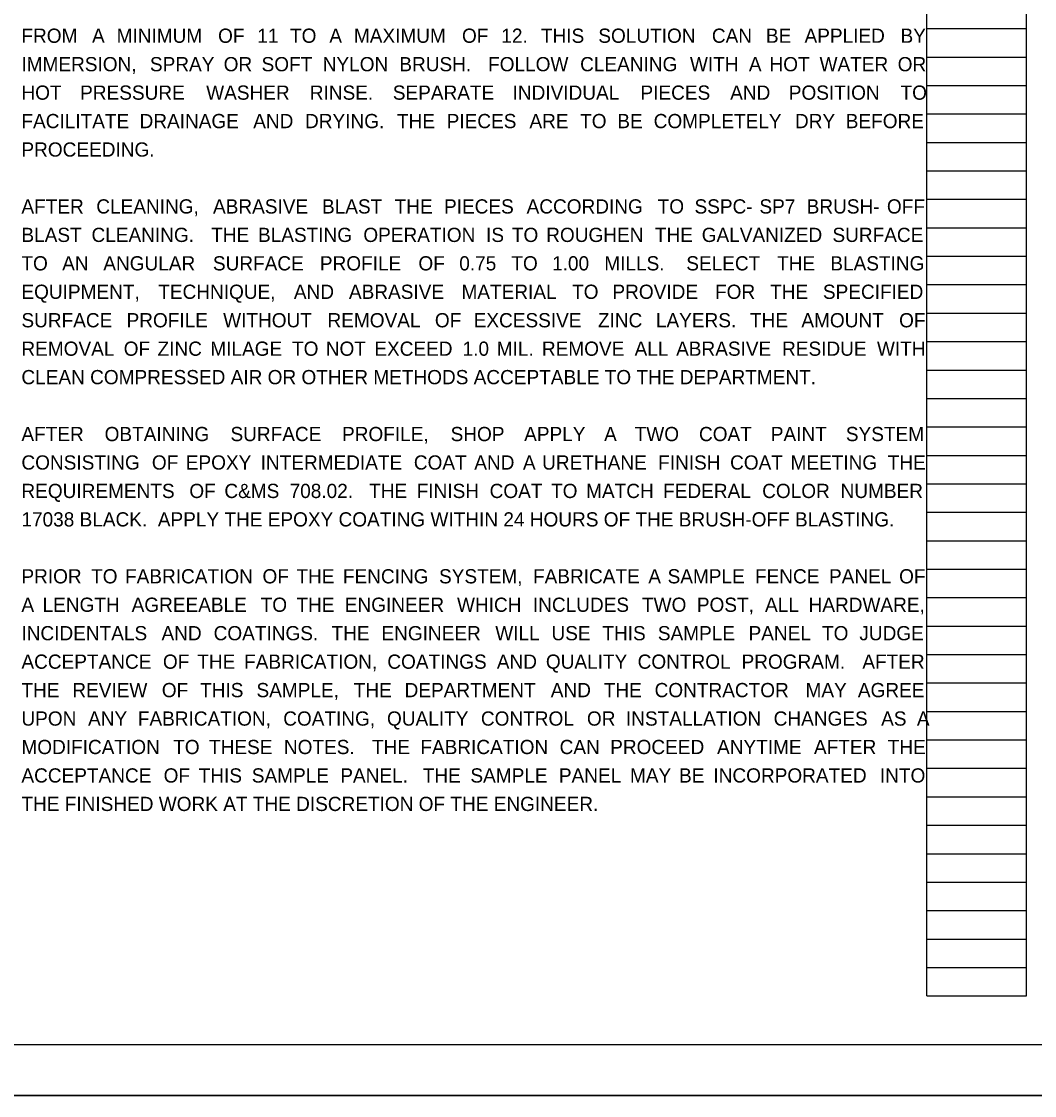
# Model space of a CAD drawing. Extents: x 0 to 34, y 0 to 22.
# Drawn here: x 12.29 to 22.27, y 0 to 10.57 of the extents above; entities that cross this region are included whole.
import ezdxf

# ---------------------------------------------------------------- set-up
doc = ezdxf.new("R2010")
doc.units = 0
for name, color, linetype in [('SC_Scratch1', 7, 'Continuous'), ('SH_Border', 7, 'Continuous'), ('SH_Cut_Line', 7, 'Continuous'), ('SH_Text', 7, 'Continuous')]:
    doc.layers.add(name, color=color, linetype=linetype)

msp = doc.modelspace()

# ---------------------------------------------------------------- linework, layer by layer
at = {"layer": 'SC_Scratch1'}
for p, q in [((21.207, 0.98), (21.207, 21.14)), ((22.187, 0.98), (22.187, 21.14)), ((21.207, 10.5), (22.187, 10.5)), ((21.207, 10.22), (22.187, 10.22)), ((21.207, 9.94), (22.187, 9.94)), ((21.207, 9.66), (22.187, 9.66)), ((21.207, 9.38), (22.187, 9.38)), ((21.207, 9.1), (22.187, 9.1)), ((21.207, 8.82), (22.187, 8.82)), ((21.207, 8.54), (22.187, 8.54)), ((21.207, 8.26), (22.187, 8.26)), ((21.207, 7.98), (22.187, 7.98)), ((21.207, 7.7), (22.187, 7.7)), ((21.207, 7.42), (22.187, 7.42)), ((21.207, 7.14), (22.187, 7.14)), ((21.207, 6.86), (22.187, 6.86)), ((21.207, 6.58), (22.187, 6.58)), ((21.207, 6.3), (22.187, 6.3)), ((21.207, 6.02), (22.187, 6.02)), ((21.207, 5.74), (22.187, 5.74)), ((21.207, 5.46), (22.187, 5.46)), ((21.207, 5.18), (22.187, 5.18)), ((21.207, 4.9), (22.187, 4.9)), ((21.207, 4.62), (22.187, 4.62)), ((21.207, 4.34), (22.187, 4.34)), ((21.207, 4.06), (22.187, 4.06)), ((21.207, 3.78), (22.187, 3.78)), ((21.207, 3.5), (22.187, 3.5)), ((21.207, 3.22), (22.187, 3.22)), ((21.207, 2.94), (22.187, 2.94)), ((21.207, 2.66), (22.187, 2.66)), ((21.207, 2.38), (22.187, 2.38)), ((21.207, 2.1), (22.187, 2.1)), ((21.207, 1.82), (22.187, 1.82)), ((21.207, 1.54), (22.187, 1.54)), ((21.207, 1.26), (22.187, 1.26)), ((21.207, 0.98), (22.187, 0.98))]:
    msp.add_line(p, q, dxfattribs=at)
msp.add_lwpolyline([(0, 22), (34, 22), (34, 0), (0, 0)], close=True, dxfattribs=at)
at = {"layer": 'SH_Border'}
msp.add_lwpolyline([(1.5, 21.5), (33.5, 21.5), (33.5, 0.5), (1.5, 0.5)], close=True, dxfattribs=at)
at = {"layer": 'SH_Cut_Line'}
msp.add_lwpolyline([(0, 0), (34, 0), (34, 22), (0, 22)], close=True, dxfattribs=at)

# ---------------------------------------------------------------- texts
at = {"layer": 'SH_Text'}
for s, p in [('FROM ', (12.293, 10.36)), ('A ', (12.988, 10.36)), ('MINIMUM ', (13.23, 10.36)), ('OF ', (14.229, 10.36)), ('11 ', (14.615, 10.36)), ('TO ', (14.937, 10.36)), ('A ', (15.324, 10.36)), ('MAXIMUM ', (15.566, 10.36)), ('OF ', (16.63, 10.36)), ('12. ', (17.017, 10.36)), ('THIS ', (17.407, 10.36)), ('SOLUTION ', (17.972, 10.36)), ('CAN ', (19.09, 10.36)), ('BE ', (19.622, 10.36)), ('APPLIED ', (20.002, 10.36)), ('BY ', (20.947, 10.36)), ('IMMERSION, ', (12.293, 10.08)), ('SPRAY ', (13.558, 10.08)), ('OR ', (14.284, 10.08)), ('SOFT ', (14.657, 10.08)), ('NYLON ', (15.259, 10.08)), ('BRUSH.  ', (16.013, 10.08)), ('FOLLOW ', (16.887, 10.08)), ('CLEANING ', (17.793, 10.08)), ('WITH ', (18.874, 10.08)), ('A ', (19.454, 10.08)), ('HOT ', (19.657, 10.08)), ('WATER ', (20.15, 10.08)), ('OR ', (20.919, 10.08)), ('HOT ', (12.293, 9.8)), ('PRESSURE ', (12.871, 9.8)), ('WASHER ', (14.112, 9.8)), ('RINSE. ', (15.132, 9.8)), ('SEPARATE ', (15.949, 9.8)), ('INDIVIDUAL ', (17.128, 9.8)), ('PIECES ', (18.387, 9.8)), ('AND ', (19.27, 9.8)), ('POSITION ', (19.847, 9.8)), ('TO ', (20.947, 9.8)), ('FACILITATE ', (12.293, 9.52)), ('DRAINAGE ', (13.456, 9.52)), ('AND ', (14.575, 9.52)), ('DRYING. ', (15.085, 9.52)), ('THE ', (15.99, 9.52)), ('PIECES ', (16.479, 9.52)), ('ARE ', (17.294, 9.52)), ('TO ', (17.793, 9.52)), ('BE ', (18.159, 9.52)), ('COMPLETELY ', (18.517, 9.52)), ('DRY ', (19.908, 9.52)), ('BEFORE ', (20.408, 9.52)), ('PROCEEDING. ', (12.293, 9.24)), ('AFTER ', (12.293, 8.68)), ('CLEANING, ', (13.03, 8.68)), ('ABRASIVE ', (14.179, 8.68)), ('BLAST ', (15.252, 8.68)), ('THE ', (15.967, 8.68)), ('PIECES ', (16.453, 8.68)), ('ACCORDING ', (17.266, 8.68)), ('TO ', (18.556, 8.68)), ('SSPC-', (18.919, 8.68)), ('SP7 ', (19.558, 8.68)), ('BRUSH-', (20.023, 8.68)), ('OFF ', (20.813, 8.68)), ('BLAST ', (12.293, 8.4)), ('CLEANING.  ', (12.983, 8.4)), ('THE ', (14.161, 8.4)), ('BLASTING ', (14.622, 8.4)), ('OPERATION ', (15.659, 8.4)), ('IS ', (16.867, 8.4)), ('TO ', (17.121, 8.4)), ('ROUGHEN ', (17.459, 8.4)), ('THE ', (18.529, 8.4)), ('GALVANIZED ', (18.99, 8.4)), ('SURFACE ', (20.277, 8.4)), ('TO ', (12.293, 8.12)), ('AN ', (12.694, 8.12)), ('ANGULAR ', (13.099, 8.12)), ('SURFACE ', (14.178, 8.12)), ('PROFILE ', (15.231, 8.12)), ('OF ', (16.201, 8.12)), ('0.75 ', (16.603, 8.12)), ('TO ', (17.116, 8.12)), ('1.00 ', (17.517, 8.12)), ('MILLS.  ', (18.031, 8.12)), ('SELECT ', (18.838, 8.12)), ('THE ', (19.732, 8.12)), ('BLASTING ', (20.256, 8.12)), ('EQUIPMENT, ', (12.293, 7.84)), ('TECHNIQUE, ', (13.64, 7.84)), ('AND ', (14.975, 7.84)), ('ABRASIVE ', (15.517, 7.84)), ('MATERIAL ', (16.625, 7.84)), ('TO ', (17.714, 7.84)), ('PROVIDE ', (18.111, 7.84)), ('FOR ', (19.121, 7.84)), ('THE ', (19.663, 7.84)), ('SPECIFIED ', (20.183, 7.84)), ('SURFACE ', (12.293, 7.56)), ('PROFILE ', (13.328, 7.56)), ('WITHOUT ', (14.279, 7.56)), ('REMOVAL ', (15.306, 7.56)), ('OF ', (16.363, 7.56)), ('EXCESSIVE ', (16.745, 7.56)), ('ZINC ', (17.968, 7.56)), ('LAYERS. ', (18.539, 7.56)), ('THE ', (19.465, 7.56)), ('AMOUNT ', (19.971, 7.56)), ('OF ', (20.933, 7.56)), ('REMOVAL ', (12.293, 7.28)), ('OF ', (13.3, 7.28)), ('ZINC ', (13.633, 7.28)), ('MILAGE ', (14.153, 7.28)), ('TO ', (14.957, 7.28)), ('NOT ', (15.289, 7.28)), ('EXCEED ', (15.767, 7.28)), ('1.0 ', (16.636, 7.28)), ('MIL. ', (16.972, 7.28)), ('REMOVE ', (17.417, 7.28)), ('ALL ', (18.329, 7.28)), ('ABRASIVE ', (18.738, 7.28)), ('RESIDUE ', (19.781, 7.28)), ('WITH ', (20.715, 7.28)), ('CLEAN COMPRESSED AIR OR OTHER METHODS ACCEPTABLE TO THE DEPARTMENT.', (12.293, 7)), ('AFTER ', (12.293, 6.44)), ('OBTAINING ', (13.112, 6.44)), ('SURFACE ', (14.351, 6.44)), ('PROFILE, ', (15.449, 6.44)), ('SHOP ', (16.518, 6.44)), ('APPLY ', (17.242, 6.44)), ('A ', (18.029, 6.44)), ('TWO ', (18.33, 6.44)), ('COAT ', (18.963, 6.44)), ('PAINT ', (19.67, 6.44)), ('SYSTEM ', (20.409, 6.44)), ('CONSISTING ', (12.293, 6.16)), ('OF ', (13.577, 6.16)), ('EPOXY ', (13.911, 6.16)), ('INTERMEDIATE ', (14.648, 6.16)), ('COAT ', (16.156, 6.16)), ('AND ', (16.751, 6.16)), ('A ', (17.23, 6.16)), ('URETHANE ', (17.419, 6.16)), ('FINISH ', (18.561, 6.16)), ('COAT ', (19.269, 6.16)), ('MEETING ', (19.864, 6.16)), ('THE ', (20.821, 6.16)), ('REQUIREMENTS ', (12.293, 5.88)), ('OF ', (13.946, 5.88)), ('C&MS ', (14.291, 5.88)), ('708.02.  ', (14.933, 5.88)), ('THE ', (15.716, 5.88)), ('FINISH ', (16.184, 5.88)), ('COAT ', (16.902, 5.88)), ('TO ', (17.507, 5.88)), ('MATCH ', (17.852, 5.88)), ('FEDERAL ', (18.61, 5.88)), ('COLOR ', (19.585, 5.88)), ('NUMBER ', (20.357, 5.88)), ('17038 BLACK.  APPLY THE EPOXY COATING WITHIN 24 HOURS OF THE BRUSH-OFF BLASTING. ', (12.293, 5.6)), ('PRIOR ', (12.293, 5.04)), ('TO ', (12.979, 5.04)), ('FABRICATION ', (13.313, 5.04)), ('OF ', (14.666, 5.04)), ('THE ', (15, 5.04)), ('FENCING ', (15.458, 5.04)), ('SYSTEM, ', (16.404, 5.04)), ('FABRICATE ', (17.329, 5.04)), ('A ', (18.464, 5.04)), ('SAMPLE ', (18.654, 5.04)), ('FENCE ', (19.514, 5.04)), ('PANEL ', (20.243, 5.04)), ('OF ', (20.933, 5.04)), ('A ', (12.293, 4.76)), ('LENGTH ', (12.501, 4.76)), ('AGREEABLE ', (13.378, 4.76)), ('TO ', (14.648, 4.76)), ('THE ', (15, 4.76)), ('ENGINEER ', (15.476, 4.76)), ('WHICH ', (16.581, 4.76)), ('INCLUDES ', (17.328, 4.76)), ('TWO ', (18.402, 4.76)), ('POST, ', (18.942, 4.76)), ('ALL ', (19.613, 4.76)), ('HARDWARE, ', (20.042, 4.76)), ('INCIDENTALS ', (12.293, 4.48)), ('AND ', (13.672, 4.48)), ('COATINGS. ', (14.185, 4.48)), ('THE ', (15.346, 4.48)), ('ENGINEER ', (15.837, 4.48)), ('WILL ', (16.958, 4.48)), ('USE ', (17.511, 4.48)), ('THIS ', (18.012, 4.48)), ('SAMPLE ', (18.558, 4.48)), ('PANEL ', (19.451, 4.48)), ('TO ', (20.174, 4.48)), ('JUDGE ', (20.542, 4.48)), ('ACCEPTANCE ', (12.293, 4.2)), ('OF ', (13.686, 4.2)), ('THE ', (14.024, 4.2)), ('FABRICATION, ', (14.485, 4.2)), ('COATINGS ', (15.895, 4.2)), ('AND ', (16.973, 4.2)), ('QUALITY ', (17.456, 4.2)), ('CONTROL ', (18.359, 4.2)), ('PROGRAM.  ', (19.382, 4.2)), ('AFTER ', (20.571, 4.2)), ('THE ', (12.293, 3.92)), ('REVIEW ', (12.794, 3.92)), ('OF ', (13.675, 3.92)), ('THIS ', (14.052, 3.92)), ('SAMPLE, ', (14.607, 3.92)), ('THE ', (15.564, 3.92)), ('DEPARTMENT ', (16.065, 3.92)), ('AND ', (17.504, 3.92)), ('THE ', (18.026, 3.92)), ('CONTRACTOR ', (18.526, 3.92)), ('MAY ', (20.012, 3.92)), ('AGREE ', (20.527, 3.92)), ('UPON ', (12.293, 3.64)), ('ANY ', (12.949, 3.64)), ('FABRICATION, ', (13.439, 3.64)), ('COATING, ', (14.87, 3.64)), ('QUALITY ', (15.892, 3.64)), ('CONTROL ', (16.816, 3.64)), ('OR ', (17.86, 3.64)), ('INSTALLATION ', (18.244, 3.64)), ('CHANGES ', (19.698, 3.64)), ('AS ', (20.756, 3.64)), ('A ', (21.108, 3.64)), ('MODIFICATION ', (12.293, 3.36)), ('TO ', (13.787, 3.36)), ('THESE ', (14.14, 3.36)), ('NOTES.  ', (14.877, 3.36)), ('THE ', (15.744, 3.36)), ('FABRICATION ', (16.22, 3.36)), ('CAN ', (17.591, 3.36)), ('PROCEED ', (18.089, 3.36)), ('ANYTIME ', (19.141, 3.36)), ('AFTER ', (20.095, 3.36)), ('THE ', (20.821, 3.36)), ('ACCEPTANCE ', (12.293, 3.08)), ('OF ', (13.693, 3.08)), ('THIS ', (14.038, 3.08)), ('SAMPLE ', (14.561, 3.08)), ('PANEL.  ', (15.432, 3.08)), ('THE ', (16.244, 3.08)), ('SAMPLE ', (16.713, 3.08)), ('PANEL ', (17.584, 3.08)), ('MAY ', (18.284, 3.08)), ('BE ', (18.767, 3.08)), ('INCORPORATED ', (19.105, 3.08)), ('INTO ', (20.744, 3.08)), ('THE FINISHED WORK AT THE DISCRETION OF THE ENGINEER.', (12.293, 2.8))]:
    msp.add_text(s, height=0.14, dxfattribs=at).set_placement(p)

doc.saveas('drawing.dxf')
